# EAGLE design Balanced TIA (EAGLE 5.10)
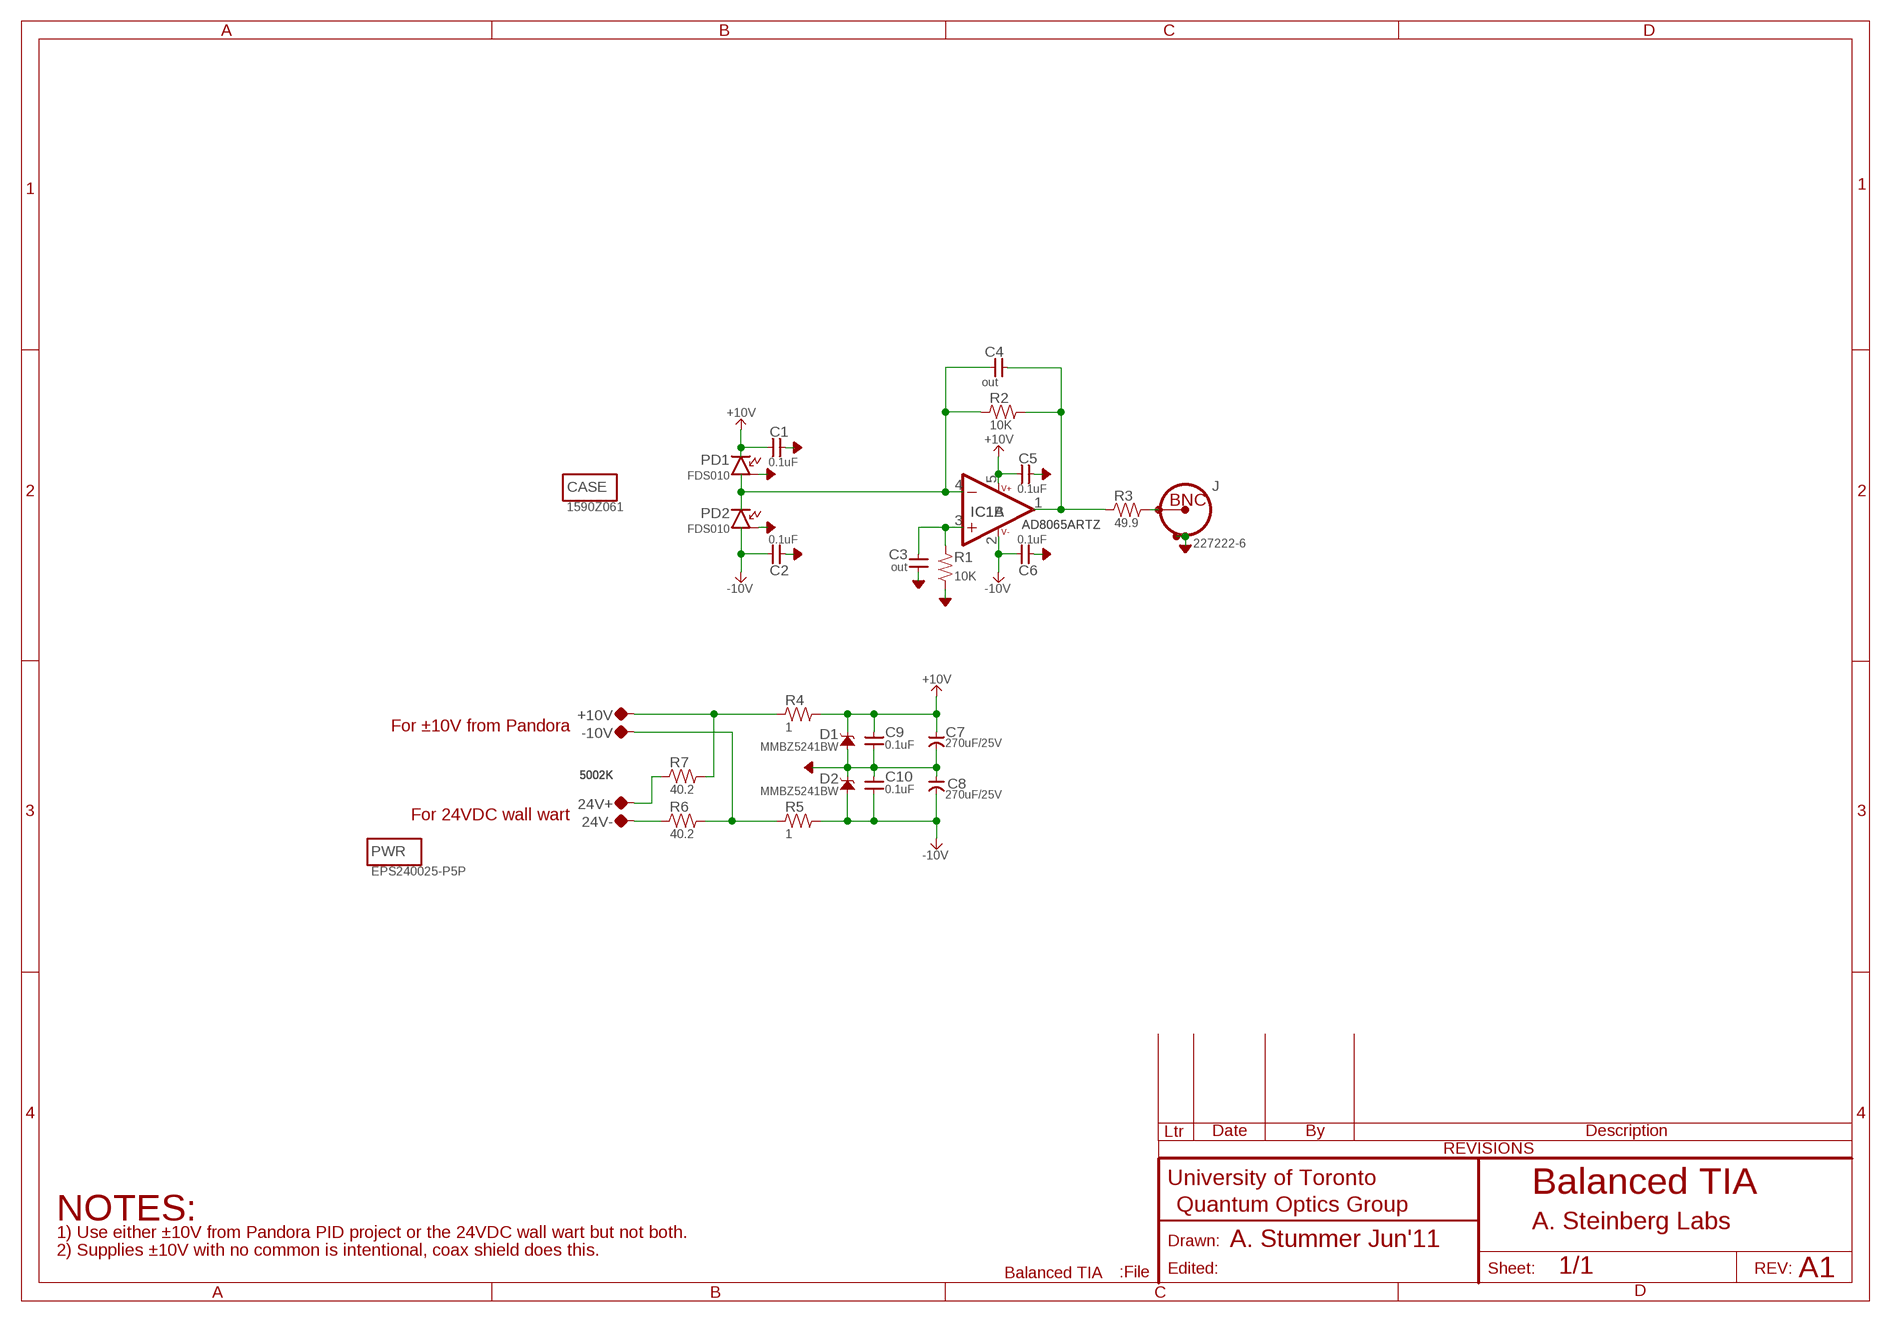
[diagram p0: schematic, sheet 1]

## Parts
24V+  5002K  TP-0.042B  [TP-0.042B]
24V-  5002K  TP-0.042B  [TP-0.042B]
+10V  5002K  TP-0.042B  [TP-0.042B]
-10V  5002K  TP-0.042B  [TP-0.042B]
C1  0.1uF  CAP-H-0805  [2012(0805)]
C2  0.1uF  CAP-H-0805  [2012(0805)]
C3  out  CAP-V-0805  [2012(0805)]
C4  out  CAP-H-0805  [2012(0805)]
C5  0.1uF  CAP-H-0805  [2012(0805)]
C6  0.1uF  CAP-H-0805  [2012(0805)]
C7  270uF/25V  CAP-POL--5MM_C-C  [CAP:5MM-THROUGH]
C8  270uF/25V  CAP-POL--5MM_C-C  [CAP:5MM-THROUGH]
C9  0.1uF  CAP-V-0805  [2012(0805)]
C10  0.1uF  CAP-V-0805  [2012(0805)]
CASE  1590Z061  MISC  [MISC]
D1  MMBZ5241BW  ZENER-SOT23  [SOT23]
D2  MMBZ5241BW  ZENER-SOT23  [SOT23]
IC1  AD8065ARTZ  OPAMP-SOT23-5  [SOT23-5]
J  227222-6  CONN:BNC-TYPE2VERT  [CONN:BNC-AMP-TYPE2VERT]
PD1  FDS010  PHOTODIODE:3TERM-FDS010  [PHOTODIODE:3TERM]
PD2  FDS010  PHOTODIODE:3TERM-FDS010  [PHOTODIODE:3TERM]
PWR  EPS240025-P5P  MISC  [MISC]
R1  10K  R-V-0805  [2012(0805)]
R2  10K  R-H-0805  [2012(0805)]
R3  49.9  R-H-0805  [2012(0805)]
R4  1  R-H-0805  [2012(0805)]
R5  1  R-H-0805  [2012(0805)]
R6  40.2  R-H-0805  [2012(0805)]
R7  40.2  R-H-0805  [2012(0805)]

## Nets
+10V: C1.1 C5.1 C7.+(POS) C9.2 D1.3(C) IC1.5(B:V++) PD1.CATHODE R4.2
-10V: C2.1 C6.1 C8.-(NEG) C10.1 D2.1(A) IC1.2(B:V-) PD2.ANODE R5.2
AGND: C1.2 C2.2 C3.1 C5.2 C6.2 C7.-(NEG) C8.+(POS) C9.1 C10.2 D1.1(A) D2.3(C) J.SHIELD1 J.SHIELD2 PD1.CASE PD2.CASE R1.1
N$1 [PD]: C4.1 IC1.4(A:-IN) PD1.ANODE PD2.CATHODE R2.1
N$2: C4.2 IC1.1(A:OUT) R2.2 R3.1
N$3: J.CONDUCTOR R3.2
N$4: C3.2 IC1.3(A:+IN) R1.2
N$5: +10V.TP R4.1 R7.2
N$6: -10V.TP R5.1 R6.2
N$7: 24V+.TP R7.1
N$8: 24V-.TP R6.1

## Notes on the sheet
- For ±10V from Pandora
- For 24VDC wall wart
- Balanced TIA
- NOTES:
- A. Steinberg Labs
- 1) Use either ±10V from Pandora PID project or the 24VDC wall wart but not both.
- A. Stummer Jun'11
- 2) Supplies ±10V with no common is intentional, coax shield does this.
- A1

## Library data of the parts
24V+ 24V- +10V -10V = QuantumOptics:TP: Testpoint, either SMT pad, small hole or loop style TP such as Keystone 5002K (0.042").
C1 C2 C4-C6 = QuantumOptics:CAP-H-: Cap, SMT and Through-hole, 0402 and up.
C3 C9 C10 = QuantumOptics:CAP-V-: Cap, SMT and Through-hole, 0402 and up.
C7 C8 = QuantumOptics:CAP-POL-: Capacitor, Polarized, SMT 0805 and up, probably tantalum.
CASE PWR = QuantumOptics:MISC: Miscellaneous Part, just a placeholder for miscellaeous parts
D1 D2 = QuantumOptics:ZENER: Zener
IC1 = QuantumOptics:OPAMP: Op Amp, generic, pick the right package. e.g. AD8605: SOT-23-5, RRIO, 10MHz, Ib = 1pA, Vio < 65uV, 2.7-5.5V.
J = QuantumOptics:CONN:BNC: BNC PCB, horizontal or vertical, e.g. Horiz: Amp (5)227677-1, nut 1-329631-2, shoulder washer 330620, vert isolated 5227222-6, http://catalog.tycoelectronics.com/TE/bin/TE.Connect?C=1&M=BYPN&TCPN=5227222-6&RQPN=5227222-6 ...
PD1 PD2 = QuantumOptics:PHOTODIODE:3TERM: Photodiode FDS010, Thorlabs
R1 = QuantumOptics:R-V-*: Resistor, SMT & Through-Hole, vertical symbol
R2-R7 = QuantumOptics:R-H-*: Resistor, SMT & Through-Hole, horizontal symbol

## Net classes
0 default: width 0.178 mm, drill 0.508 mm, clearance 0.178 mm
1 PD: width 0.178 mm, drill 0.508 mm, clearance 0.762 mm

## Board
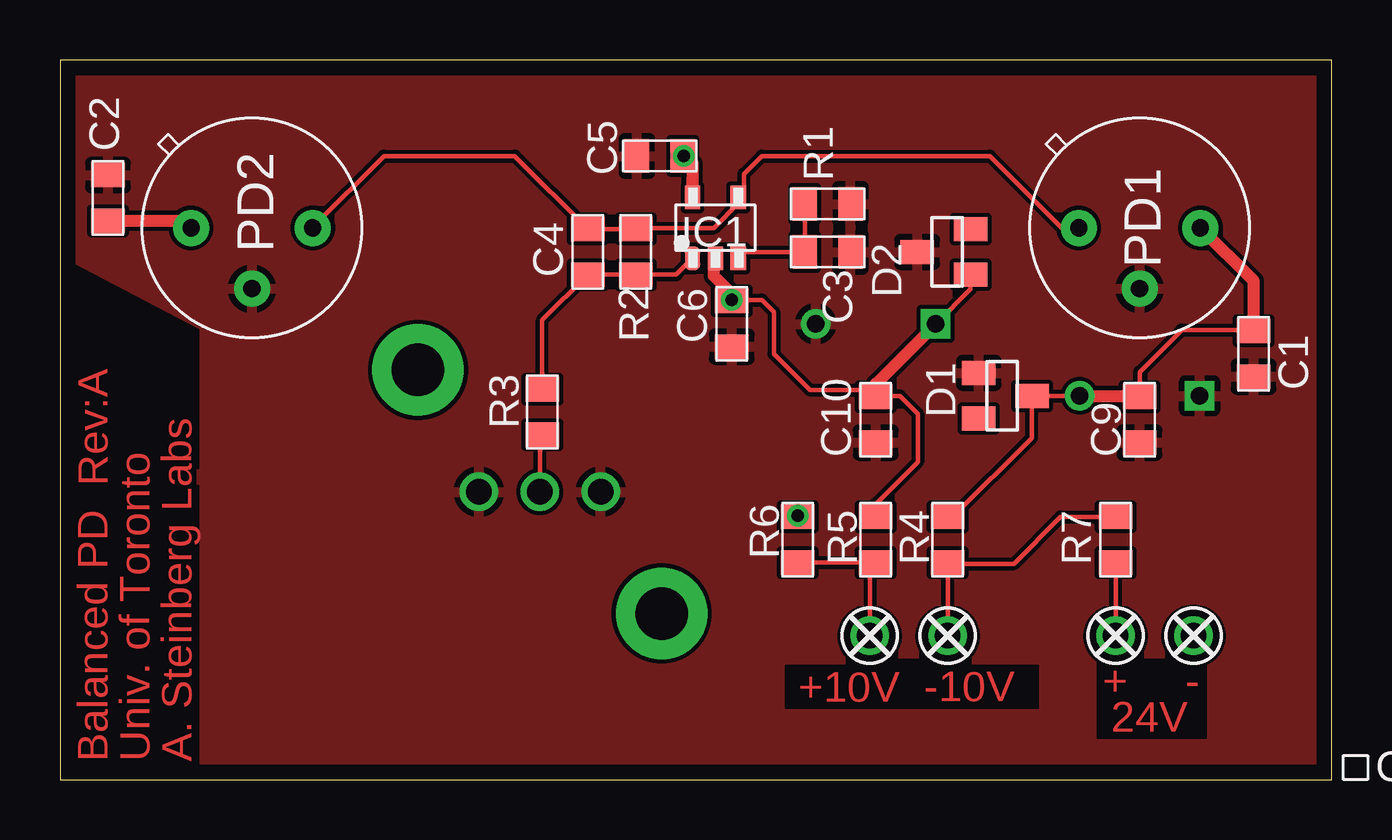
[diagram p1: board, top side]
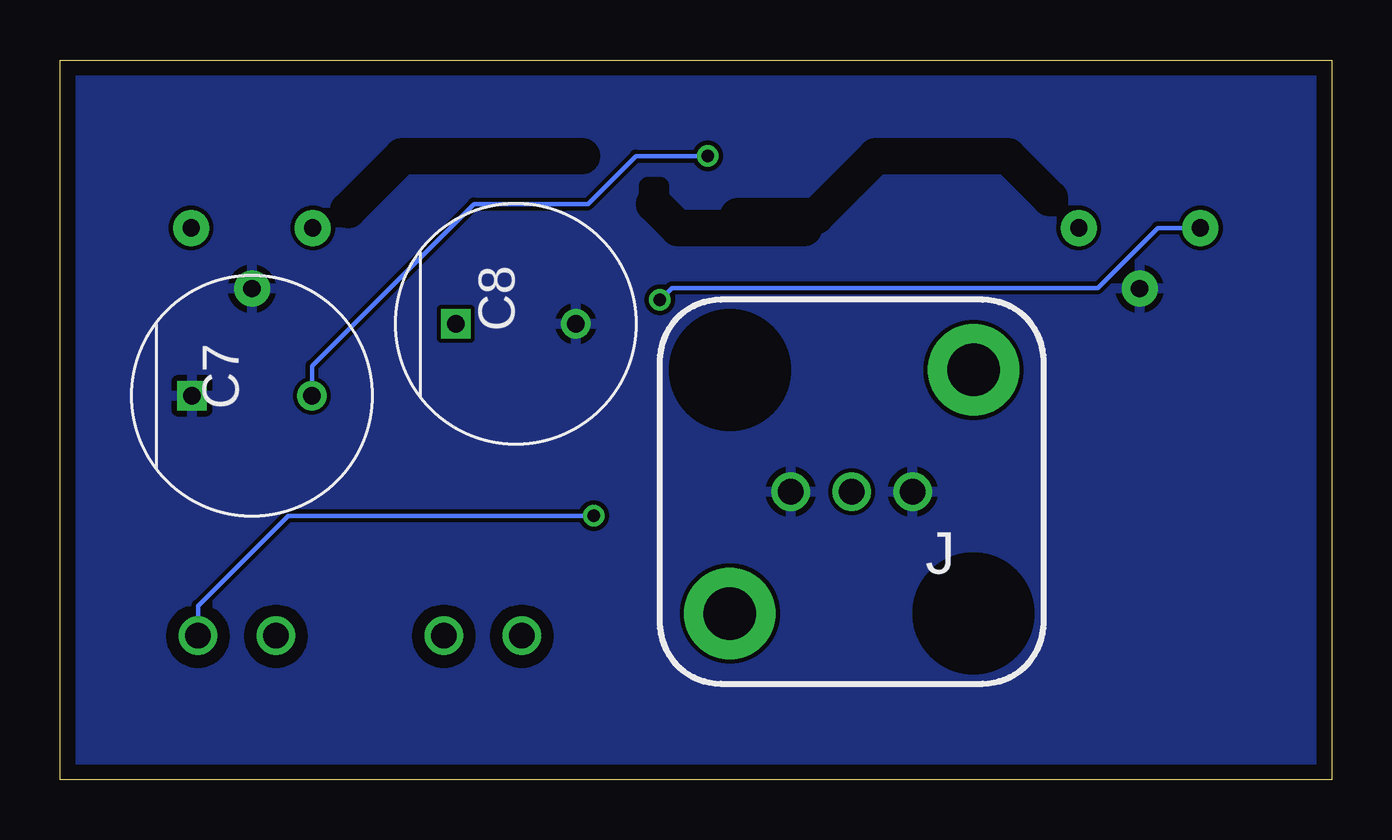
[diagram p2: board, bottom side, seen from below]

Size 53 x 30 mm. Coordinates in mm from the lower left corner, seen from the top.
Outline: 53,0 53,30 0,30 0,0 53,0
Copper layers (1+16): Top 0.035mm / dielectric 1.5mm / Bottom 0.035mm
Design rules "DRC standard check": minimum track width 7mil, minimum drill 20mil, track to track 7mil, track to pad 7mil, pad to pad 7mil, via to via 7mil, smd to smd 0mil, copper to edge 25mil, drill to drill 8mil, minimum pad ring 10mil, minimum via ring 8mil, stop-mask expansion 4mil, vias tented up to drill 0mil, thermal gap 10mil
tRestrict: 14 lines
bRestrict: 14 lines

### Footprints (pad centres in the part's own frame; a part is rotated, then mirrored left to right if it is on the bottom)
TP-0.042B = drill 1.067 round: TP 0,0
2012(0805) = smd 1.016 x 1.397: 1 -0.953,0; 2 0.953,0
CAP:5MM-THROUGH = drill 0.711 round: + 2.5,0 | drill 0.711 square: - -2.5,0
SOT23 = smd 1 x 1.4: 1 -0.953,-0.953; 2 0.953,-0.953; 3 0,1.27
SOT23-5 = smd 0.635 x 0.991: 1 -0.635,-1.27; 2 0.318,-1.27; 3 1.27,-1.27; 4 1.27,1.27; 5 -0.635,1.27
CONN:BNC-AMP-TYPE2VERT = drill 1.067 round: CONDUCTOR 0,0; SHIELD1 -2.54,0; SHIELD2 2.54,0 | drill 2.184 pad 3.81 round: MTG1 -5.08,-5.08; MTG2 5.08,5.08
PHOTODIODE:3TERM = drill 0.711 pad 1.5 round: ANODE -2.54,0; CASE 0,-2.54; CATHODE 2.54,0

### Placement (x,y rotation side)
24V+  44,6 270 top
24V-  47.25,6 270 top
+10V  37,6 270 top
-10V  33.75,6 270 top
C1  49.75,17.75 270 top
C2  2,24.25 90 top
C3  32,22 180 top
C4  22,22 270 top
C5  25,26 180 top
C6  28,19 270 top
C7  45,16 0 bottom
C8  34,19 0 bottom
C9  45,15 90 top
C10  34,15 270 top
CASE  54,0.5 0 top
D1  39.25,16 270 top
D2  37,22 90 top
IC1  27,23 0 top
J  20,12 180 bottom
PD1  45,23 0 top
PD2  8,23 0 top
PWR  not placed on the board
R1  32,24 180 top
R2  24,22 270 top
R3  20.1,15.32 270 top
R4  37,10 90 top
R5  34,10 90 top
R6  30.75,10 270 top
R7  44,10 90 top
U$10  [TITLEBLOCK_PCB]  not placed on the board

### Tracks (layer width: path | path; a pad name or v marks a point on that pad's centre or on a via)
+10V  (via drill 0.51)
  Top 0.18: C9.2 45,16 45,17 46.75,18.75 49.7,18.75 C1.1 | C7.+ D1.3 40.5,15.98 40.5,14.25 37.2,10.95 R4.2 | 26.05,26 C5.1 v26,26
  Top 0.5: C7.+ 45,16 | C5.1 26.36,25.68 IC1.5 26.36,25.11 | C1.1 49.75,20.79 PD1.CATHODE
  Bottom 0.18: C7.+ 42.5,17.25 35.75,24 31,24 29,26 v26,26
-10V  (via drill 0.51)
  Top 0.18: D2.1 37.95,20.45 C8.- | R5.2 34,11.5 35.75,13.25 35.75,15.25 35,16 34.05,16 C10.1 33.7,16.25 31.25,16.25 29.75,17.75 29.75,19.5 29.25,20 28.05,20 C6.1 v28,20 28,20.25 | 27.25,21.66 IC1.2
  Top 0.5: C10.1 34,16.5 C8.- | 28,20.25 27.25,21 27.25,21.66 | C2.1 5.16,23.3 PD2.ANODE
  Bottom 0.18: PD2.ANODE 7.25,23 9.75,20.5 27.5,20.5 v28,20
AGND
  pour Bottom (rank 2): 53,0 53,30 0,30 0,0
  pour Top (rank 2): 53,0 53,30 0,30 0,0
N$1
  Top 0.18: PD1.ANODE 41.75,23 38.75,26 29.25,26 28.5,25.25 28.5,24.5 IC1.4 28.27,24.02 27.25,23 24.05,23 R2.1 C4.1 18.95,26 13.5,26 10.54,23.04 PD2.CATHODE
N$2
  Top 0.18: IC1.1 25.68,21.05 R2.2 C4.2 20.1,19.15 R3.1
N$3
  Top 0.18: R3.2 20,14.27 J.CONDUCTOR
N$4
  Top 0.18: R1.2 C3.2 28.54,22 IC1.3
N$5
  Top 0.18: +10V.TP R4.1 37.05,9 39.75,9 41.7,10.95 R7.2
N$6
  Top 0.18: R6.2 R5.1 33.75,8.8 -10V.TP
N$7
  Top 0.18: 24V+.TP R7.1
N$8  (via drill 0.51)
  Top 0.18: R6.1 v30.75,11
  Bottom 0.18: v30.75,11 43.5,11 47.25,7.25 24V-.TP

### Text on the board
Top: + | - | +10V | -10V | 24V | Balanced PD Rev:A | Univ. of Toronto | A. Steinberg Labs
Reference: 8 | 37mm | 8 | 7 | 23 | 12 | 20 | Balanced TIA | A. Stummer Jun'11 | A1 | 0.18mm | 0.5mm | 0.18mm | 0.25mm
